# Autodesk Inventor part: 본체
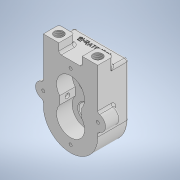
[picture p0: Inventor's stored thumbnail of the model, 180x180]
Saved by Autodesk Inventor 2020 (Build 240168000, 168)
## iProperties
Created: 2024-03
Part Number: 본체
Material: 일반
Document SubType Name: Modeling
Designer: oem
Density: 1 g/cm^3
Appearance: 기본값
Author: oem
## Parameters: d1 = 103 mm, d3 = 0, d8 = 12 mm, d9 = 0, d10 = 52 mm, d11 = 32 mm, d12 = 35 mm, d13 = 6 mm, d14 = 0, d16 = 0, d18 = 15 mm, d20 = 36 mm, d23 = 7.3 mm, d26 = 36 mm, d30 = 14 mm, d31 = 60 deg, d32 = 68 mm, d33 = 90 deg, d34 = 90 deg, d36 = 63.5 mm, d37 = 28 mm, d38 = 0, d41 = 25 mm, d42 = 8 mm, d43 = 6 mm, d44 = 6 mm, d46 = 10 mm, d48 = 25 mm, d49 = 0, d50 = 0, d51 = 0, d52 = 0, d53 = 11.835 mm, d54 = 12 mm, d55 = 4 mm, d56 = 2 mm, d57 = 90 deg, d58 = 16 mm, d59 = 118 deg, d60 = 11.835 mm, d61 = 12 mm, d62 = 4 mm, d63 = 2 mm, d64 = 90 deg, d65 = 16 mm, d66 = 118 deg, d68 = 63.5 mm, d71 = 90 deg, d72 = 4.134 mm, d74 = 4 mm, d75 = 2 mm, d76 = 90 deg, d77 = 12 mm, d78 = 118 deg, d79 = 26 mm, d80 = 26 mm, d81 = 4.134 mm, d83 = 4 mm, d84 = 2 mm, d85 = 90 deg, d86 = 12 mm, d87 = 118 deg, d88 = 35 mm, d89 = 30 deg, d90 = 0.7 mm, d91 = 25 mm, d92 = 7.3 mm, d93 = 42 mm, d96 = 360 deg, d98 = 3.242 mm, d99 = 8 mm, d100 = 4 mm, d101 = 2 mm, d102 = 90 deg, d104 = 118 deg, d105 = 3 mm, d106 = 3 mm, d107 = 3 mm, d108 = 3 mm, d109 = 1 mm, d110 = 2 mm, d111 = 45 deg, d112 = 35 mm, d114 = 0.5 mm, d115 = 0, d116 = 1 mm, d117 = 2 mm, d118 = 45 deg
